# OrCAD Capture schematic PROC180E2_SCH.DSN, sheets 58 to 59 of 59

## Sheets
58 47. CAN_INTERFACE: size C; title: CAN TRANSCEIVER
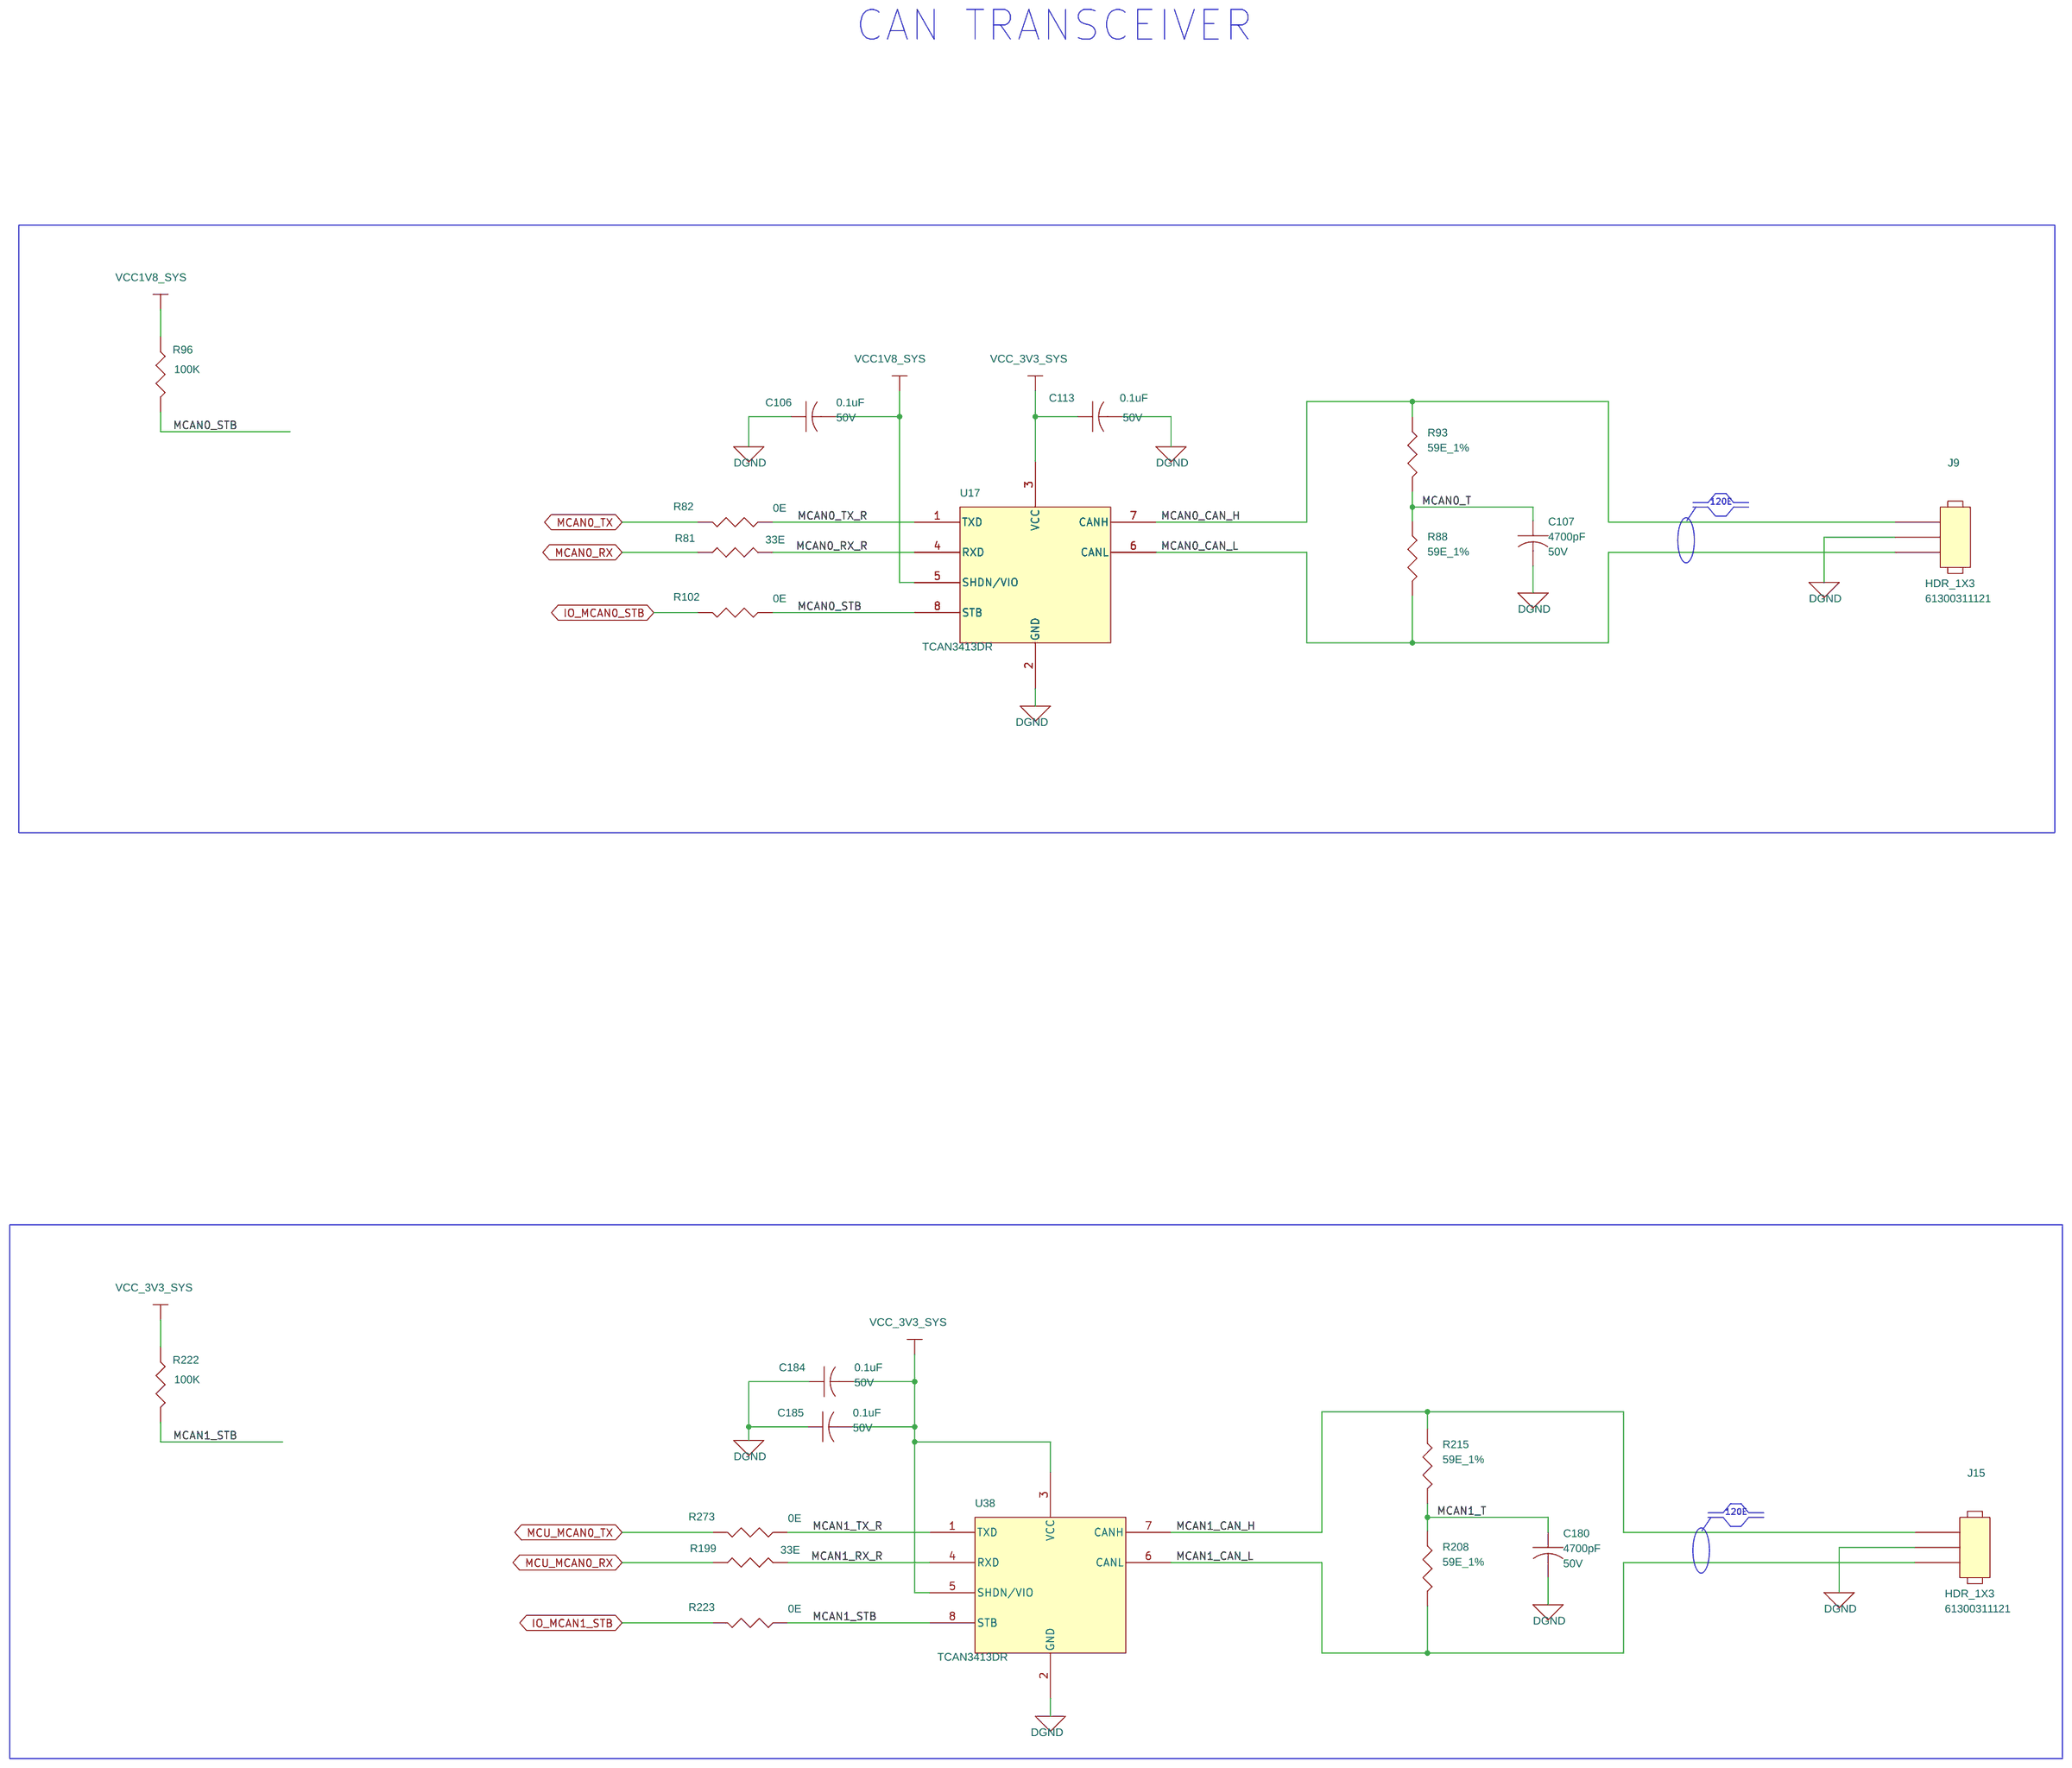
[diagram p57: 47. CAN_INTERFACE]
59 59. MOUNTING HARDWARE: title: MOUNTING HARDWARE
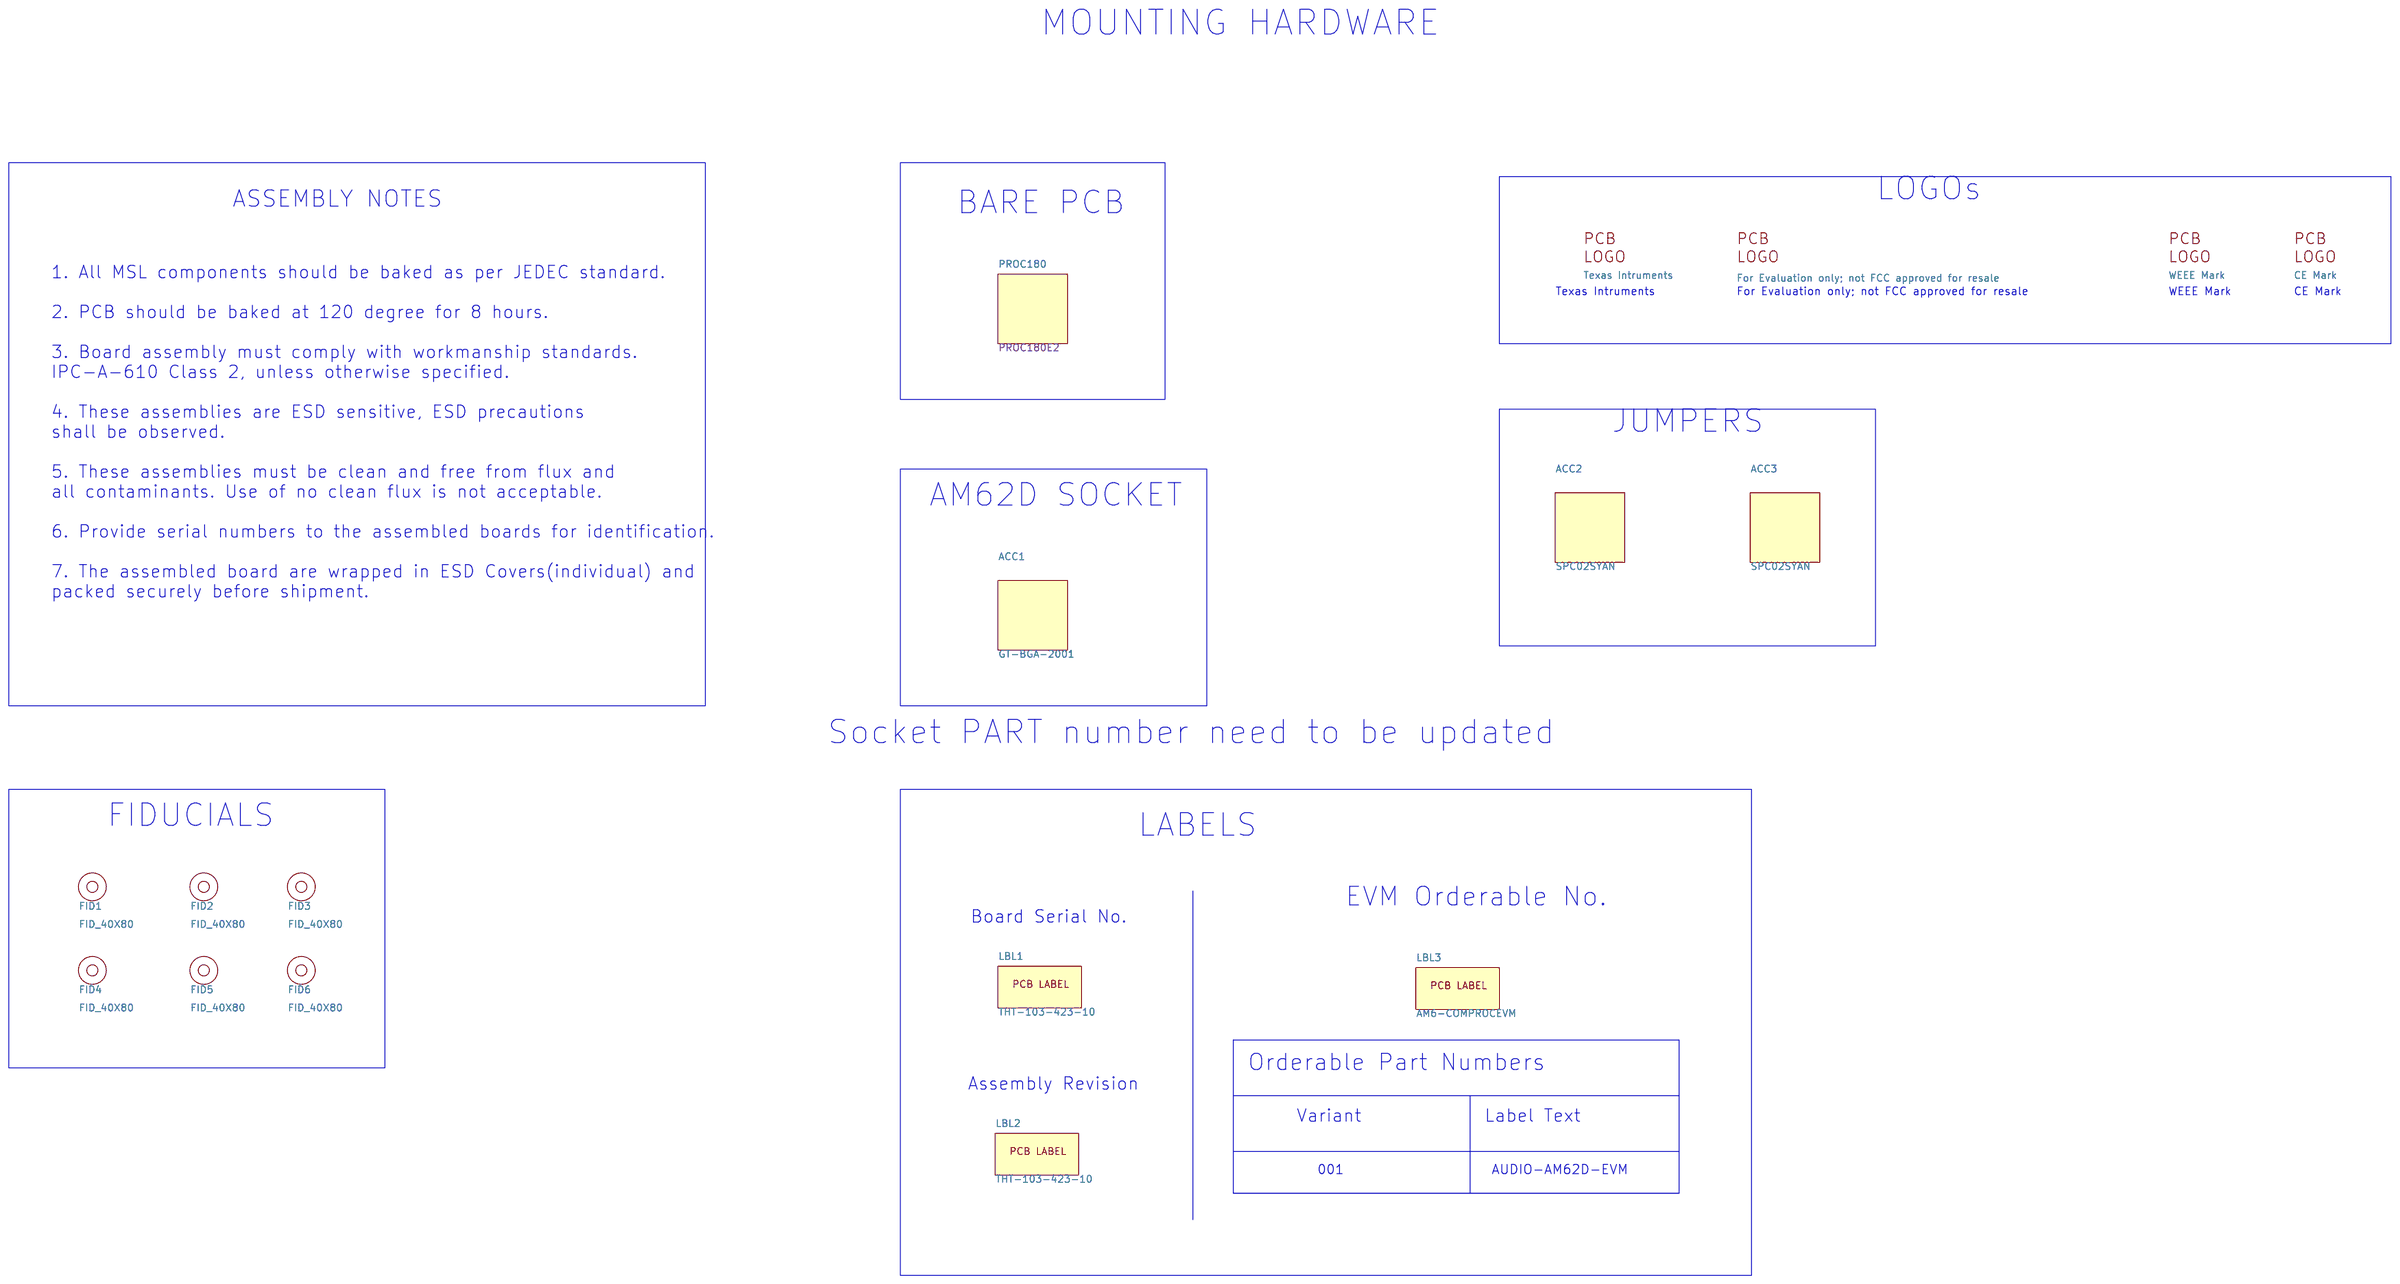
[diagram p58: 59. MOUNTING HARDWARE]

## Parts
sheet 47. CAN_INTERFACE
C106  0.1uF  [CAP0402_0-75]
C107  4700pF  [CAP0402_0-75]
C113  0.1uF  [CAP0402_0-75]
C180  4700pF  [CAP0402_0-75]
C184  0.1uF  [CAP0402_0-75]
C185  0.1uF  [CAP0402_0-75]
J9  HDR_1X3  [HDR_1X3_100_S_T]
J15  HDR_1X3  [HDR_1X3_100_S_T]
R81  33E  [RES0402_0-5]
R82  0E  [RES0402_0-5]
R88  59E_1%  [RES0402_0-5]
R93  59E_1%  [RES0402_0-5]
R96  100K  [RES0201_0-5]
R102  0E  [RES0402_0-5]
R199  33E  [RES0402_0-5]
R208  59E_1%  [RES0402_0-5]
R215  59E_1%  [RES0402_0-5]
R222  100K  [RES0201_0-5]
R223  0E  [RES0402_0-5]
R273  0E  [RES0402_0-5]
U17  TCAN3413DR  [SOIC8_1-8]
U38  TCAN3413DR  [SOIC8_1-8]
sheet 59. MOUNTING HARDWARE
ACC1  GT-BGA-2001  [BGASKT484_GT-BGA-2001_910X910_10-7]
ACC2  SPC02SYAN  [NA]
ACC3  SPC02SYAN  [NA]
FID1  FID_40X80  [FID_40X80]
FID2  FID_40X80  [FID_40X80]
FID3  FID_40X80  [FID_40X80]
FID4  FID_40X80  [FID_40X80]
FID5  FID_40X80  [FID_40X80]
FID6  FID_40X80  [FID_40X80]
LBL1  THT-103-423-10  [NA]
LBL2  THT-103-423-10  [NA]
LBL3  AM6-COMPROCEVM  [NA]
LOGO1  Texas Intruments  [TI_Stacked_Overlay_Small]
LOGO2  For Evaluation only; not FCC approved for resale  [FCC_disclaimer]
LOGO3  WEEE Mark  [TI_Stacked_Overlay_Small]
LOGO4  CE Mark  [TI_Stacked_Overlay_Small]
PCB1  PROC180

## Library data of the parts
C106 C113 C184 C185 = CAP: CAP CERAMIC 0.1uF 50V 10% X7R AUTO 0402; Automotive Alternate_mfr_name: TDK; Automotive Alternate_mfr_part_number: CGA2B1X7R1C104K050BC; Chkd/date: MANIRAJA/250221; Crtd /date: ALVY/240221; Custom_Duty: 15%; Customs_HS_Code: 85322990; Direct Alternate_mfr_name: MURATA; Direct Alternate_mfr_part_number: GCM155R71C104JA55D; Distributor_name: MOUSER; Distributor_part_number: 81-GRT155R71H104KE1D; Footprint Path: Y:\MIS_DATABASE\Library\ALTIUM_TOOL\PCB_FOOTPRINTS\Altium_Footprint_Lib.PcbLib; Height: 0.55MM; Library Path: Y:\MIS_DATABASE\Library\ALTIUM_TOOL\SCHEMATICS_PARTS\MS_DISCRETE_Library.schlib; Mfr_name: MURATA; Mfr_part_number: GRT155R71H104KE01D; Mistral Part No: 120019030005-R; Package: 0402; Part_type: CAPACITORS\CERAMIC; Project: TI_DRA821 SK EVM BRD; RoHS: RoHS; Temperature: -55°C+125°C; Tolerance: 10%; Voltage: 50V; Wattage: NA; Weight: NA; Datasheet: Y:\MIS_DATABASE\DATASHEETS\CAPACITORS\GRT155R71H104KE01.PDF
C107 C180 = CAP: CAP CERAMIC 4700pF 50V 10% X7R 0402; Automotive Alternate_mfr_name: TDK; Automotive Alternate_mfr_part_number: CGA2B2X7R1H472K050BA; Chkd/date: MANIRAJA/040419; Crtd /date: MANIRAJA/040419; Custom_Duty: 15%; Customs_HS_Code: 85322990; Direct Alternate_mfr_name: SAMSUNG; Direct Alternate_mfr_part_number: CL05B472KB5NNNC; Distributor_name: DIGIKEY; Distributor_part_number: 490-1308-1-ND; Footprint Path: Y:\MIS_DATABASE\Library\ALTIUM_TOOL\PCB_FOOTPRINTS\Altium_Footprint_Lib.PcbLib; Height: 0.55MM; Library Path: Y:\MIS_DATABASE\Library\ALTIUM_TOOL\SCHEMATICS_PARTS\MS_DISCRETE_Library.schlib; Mfr_name: MURATA; Mfr_part_number: GRM155R71H472KA01D; Mistral Part No: 120009030440-R; Package: 0402; Part_type: CAPACITORS\CERAMIC; Project: RED EYE; RoHS: RoHS; Temperature: -55°C+125°C; Tolerance: 10%; Voltage: 50V; Wattage: NA; Weight: 0.65mg; Datasheet: Y:\MIS_DATABASE\DATASHEETS\CAPACITORS\GRM155R71H472KA01.PDF
J9 J15 = HEADER_3X1: CON HDR 1X3 2.54MM PITCH ST TH; Chkd/date: VASANTHA/211015; Crtd /date: VASANTHA/211015; Custom_Duty: 24%; Customs_HS_Code: 85369090; Distributor_name: DIGIKEY; Distributor_part_number: 732-5316-ND; Height: 8.54MM; Mfr_name: WURTH ELECTRONICS INC; Mfr_part_number: 61300311121; Mistral Part No: 150015100037-R; Package: THRU-HOLE; Part_type: CONNECTOR\HEADERS; Project: CYPHY_ROADKILL; RoHS: RoHS; Temperature: NA; Tolerance: NA; Voltage: NA; Wattage: NA; Weight: NA; Datasheet: Y:\MIS_DATABASE\DATASHEETS\CONNECTORS\6130XXX.PDF
R81 R199 = RESISTOR: RES 33E 1/10W 5% 0402; Chkd/date: VASANTHA/201216; Crtd /date: GEETHA/190406; Custom_Duty: 15%; Customs_HS_Code: 85332119; Distributor_name: DIGIKEY; Distributor_part_number: P33JCT-ND; Footprint Path: Y:\MIS_DATABASE\Library\ALTIUM_TOOL\PCB_FOOTPRINTS\Altium_Footprint_Lib.PcbLib; Height: 0.40MM; Library Path: Y:\MIS_DATABASE\Library\ALTIUM_TOOL\SCHEMATICS_PARTS\MS_DISCRETE_Library.schlib; Mfr_name: PANASONIC-ECG; Mfr_part_number: ERJ-2GEJ330X; Mistral Part No: 110009030699-R; Package: 0402; Part_type: RESISTORS\FIXED; Project: RED EYE; RoHS: RoHS; Temperature: -55°C+155°C; Tolerance: 5%; Voltage: NA; Wattage: 1/10W; Weight: 0.8mg; Datasheet: Y:\MIS_DATABASE\DATASHEETS\RESISTORS\PAN-ERJSER_NOV17.PDF
R82 R102 R223 R273 = RESISTOR: RES 0E 1/10W JUMPER 0402; Chkd/date: VASANTHA/061216; Crtd /date: NAVEED/201014; Custom_Duty: 15%; Customs_HS_Code: 85332119; Distributor_name: DIGIKEY; Distributor_part_number: P0.0JCT-ND; Footprint Path: Y:\MIS_DATABASE\Library\ALTIUM_TOOL\PCB_FOOTPRINTS\Altium_Footprint_Lib.PcbLib; Height: 0.40MM; IBISSP_MODLES: VALUE REPEATING 2 TIME; Library Path: Y:\MIS_DATABASE\Library\ALTIUM_TOOL\SCHEMATICS_PARTS\MS_DISCRETE_Library.schlib; Mfr_name: PANASONIC-ECG; Mfr_part_number: ERJ-2GE0R00X; Mistral Part No: 110018030052-R; Package: 0402; Part_type: RESISTORS\FIXED; Project: AEGIS POM; RoHS: RoHS; Temperature: -55°C+155°C; Tolerance: NA; Voltage: NA; Wattage: 1/10W; Weight: 0.8mg; Datasheet: Y:\MIS_DATABASE\DATASHEETS\RESISTORS\PAN-ERJSER_NOV17.PDF
R88 R93 R208 R215 = RESISTOR: RES 59E 1/10W 1% 0402; Chkd/date: MAZHAR/151208; Crtd /date: USMAN/031208; Custom_Duty: 15%; Customs_HS_Code: 85332119; Distributor_name: DIGIKEY; Distributor_part_number: P59.0LCT-ND; Footprint Path: Y:\MIS_DATABASE\Library\ALTIUM_TOOL\PCB_FOOTPRINTS\Altium_Footprint_Lib.PcbLib; Height: 0.40MM; Library Path: Y:\MIS_DATABASE\Library\ALTIUM_TOOL\SCHEMATICS_PARTS\MS_DISCRETE_Library.schlib; Mfr_name: PANASONIC-ECG; Mfr_part_number: ERJ-2RKF59R0X; Mistral Part No: 110009031010-R; Package: 0402; Part_type: RESISTORS\FIXED; Project: KHAN_HSST; RoHS: RoHS; Temperature: -55°C+155°C; Tolerance: 1%; Voltage: NA; Wattage: 1/10W; Weight: 0.8mg; Datasheet: Y:\MIS_DATABASE\DATASHEETS\RESISTORS\PAN-ERJSER_NOV17.PDF
R96 R222 = RESISTOR: RES 100K 1/20W 5% 0201; Chkd/date: MANIRAJA/050517; Crtd /date: MANIRAJA/050517; Custom_Duty: 15%; Customs_HS_Code: 85332119; Distributor_name: DIGIKEY; Distributor_part_number: 311-100KNCT-ND; Footprint Path: Y:\MIS_DATABASE\Library\ALTIUM_TOOL\PCB_FOOTPRINTS\Altium_Footprint_Lib.PcbLib; Height: 0.26MM; Library Path: Y:\MIS_DATABASE\Library\ALTIUM_TOOL\SCHEMATICS_PARTS\MS_DISCRETE_Library.schlib; Mfr_name: YAGEO AMERICA; Mfr_part_number: RC0201JR-07100KL; Mistral Part No: 110009030176-R; Package: 0201; Part_type: RESISTORS\FIXED; Project: GOLDEN-I LITE; RoHS: RoHS; Temperature: -55°C+125°C; Tolerance: 5%; Voltage: NA; Wattage: 1/20W; Weight: 0.17mg; Datasheet: Y:\MIS_DATABASE\DATASHEETS\RESISTORS\RCXXXXL-SER_MAR18.PDF
U17 U38 = TCAN3413DR_SOIC8: IC 3.3V CAN FD TRANSCEIVERS WITH STANDBY MODE AND +/-58V BUS STANDOFF SOIC8; Crtd /date: TAMILARASU/221223; Custom_Duty: 15%; Customs_HS_Code: 85423100; Distributor_name: NA; Distributor_part_number: NA; Footprint Path: Y:\MIS_DATABASE\Library\ALTIUM_TOOL\PCB_FOOTPRINTS\Altium_Footprint_Lib.PcbLib; Height: 1.80MM; Library Path: Y:\MIS_DATABASE\Library\ALTIUM_TOOL\SCHEMATICS_PARTS\MS_TELECOM_Library.schlib; Mfr_name: TEXAS INSTRUMENTS; Mistral Part No: 140123120005-R; Package: SOIC8; Part_type: ICS\TELECOM\TRANSCEIVER; Project: AM62D-EVM; RoHS: RoHS; Temperature: -40°C+125°C; Tolerance: NA; Voltage: NA; Wattage: NA; Weight: NA; Datasheet: Y:\MIS_DATABASE\DATASHEETS\ICS\TELECOM\TCAN3413.PDF
ACC1 = ACCESSORY: ACCESSORIE BGA SOCKET AM62A SVB SoC MICROPROCESSOR FCBGA484; Chkd/date: ALVY/180422; Crtd /date: ALVY/180422; Custom_Duty: NA; Customs_HS_Code: NA; Distributor_name: NA; Distributor_part_number: NA; Footprint Path: NA; Height: 10.69MM; Library Path: NA; Mfr_name: IRONWOOD ELECTRONICS; Mistral Part No: 160022040013; Package: FCBGA484; Part_type: ACCESSORIES; Project: TI_AM62A_SVB_BRD; RoHS: NA; Temperature: NA; Tolerance: NA; Voltage: NA; Wattage: NA; Weight: NA; Datasheet: Y:\MIS_DATABASE\DATASHEETS\MISC\ACCESSORIES\GT-BGA-2001.PDF
ACC2 ACC3 = ACCESSORY: ACCESSORIE JUMPER SHORTING GOLD FLASH; Chkd/date: SUHAS\211010; Crtd /date: USMAN/301208; Distributor_name: DIGIKEY; Distributor_part_number: S9001-ND; Footprint Path: Y:\MIS_DATABASE\Library\ALTIUM_TOOL\PCB_FOOTPRINTS\Altium_Footprint_Lib.PcbLib; Library Path: Y:\MIS_DATABASE\Library\ALTIUM_TOOL\SCHEMATICS_PARTS\MS_MECHANICAL_Library.schlib; Mfr_name: SULLINS CONNECTOR; Mistral Part No: 160009030153-R; Part_type: ACCESSORIES; Project: SMART VIEW_NVR; RoHS: RoHS; Temperature: -55°C+105°C; Datasheet: Y:\MIS_DATABASE\DATASHEETS\MISC\MODULES\SPC02SYAN.PDF
FID1-FID6 = Fiducial
LBL1 LBL2 = ACCESSORY_THT-3-423-10: ACCESSORIE 1 WORKHORSE POLYSTER LABLE 0.25" X 1"; Chkd/date: MANIRAJA/270218; Crtd /date: ALVY/260218; Footprint Path: Y:\MIS_DATABASE\Library\ALTIUM_TOOL\PCB_FOOTPRINTS\Altium_Footprint_Lib.PcbLib; Library Path: Y:\MIS_DATABASE\Library\ALTIUM_TOOL\SCHEMATICS_PARTS\MS_MECHANICAL_Library.schlib; Mfr_name: BRADY; Mistral Part No: 160018020185; Part_type: ACCESSORIES; Project: TI_MAXIE_CPB
LBL3 = ACCESSORY_THT-3-423-10: ACCESSORIE 1 WORKHORSE POLYSTER LABLE 0.25" X 1"; Chkd/date: MANIRAJA/270218; Crtd /date: ALVY/260218; Footprint Path: Y:\MIS_DATABASE\Library\ALTIUM_TOOL\PCB_FOOTPRINTS\Altium_Footprint_Lib.PcbLib; Library Path: Y:\MIS_DATABASE\Library\ALTIUM_TOOL\SCHEMATICS_PARTS\MS_MECHANICAL_Library.schlib; Mfr_name: BRADY; Mfr_part_number: THT-103-423-10; Mistral Part No: 160018020185; Part_type: ACCESSORIES; Project: TI_MAXIE_CPB
LOGO1 LOGO3 LOGO4 = TI_Logo
LOGO2 = FCC_disclaimer
PCB1 = PCB_0: AM62D EVM; Mfr_part_number: PROC180E2; Mistral Part No: FY22-23/00176000401

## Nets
DGND: C106.1 C107.2 C113.2 C180.2 C184.1 C185.1 J9.2 J15.2 U17.2(GND) U38.2(GND) ; also on sheet 1 2 3 4 5 6 7 8 9 10 12 13 14 16 17 18 19 20 21 22 31 32 33 34 35 36 37 38 39 40 41 42 43 44 45 46 47 48 49 50 51 52 53 54 55 56 57
VCC1V8_SYS: C106.2 R96.1 U17.5(SHDN/VIO) ; also on sheet 1 2 4 6 7 10 20 21 22 33 37 38 39 42 43 49 50 52 53 54 55 56 57
VCC_3V3_SYS: C113.1 C184.2 C185.2 R222.1 U17.3(VCC) U38.3(VCC) U38.5(SHDN/VIO) ; also on sheet 1 2 3 6 10 14 17 18 19 20 22 31 33 37 38 40 41 42 45 46 48 49 50 51 52 53 54 55 56 57
IO_MCAN0_STB: R102.2 ; also on sheet 55
IO_MCAN1_STB: R223.2 ; also on sheet 55
MCAN0_CAN_H: J9.1 R93.1 U17.7(CANH)
MCAN0_CAN_L: J9.3 R88.2 U17.6(CANL)
MCAN0_RX: R81.1 ; also on sheet 7
MCAN0_RX_R: R81.2 U17.4(RXD)
MCAN0_STB: R96.2 R102.1 U17.8(STB)
MCAN0_T: C107.1 R88.1 R93.2
MCAN0_TX: R82.2 ; also on sheet 7
MCAN0_TX_R: R82.1 U17.1(TXD)
MCAN1_CAN_H: J15.1 R215.1 U38.7(CANH)
MCAN1_CAN_L: J15.3 R208.2 U38.6(CANL)
MCAN1_RX_R: R199.2 U38.4(RXD)
MCAN1_STB: R222.2 R223.1 U38.8(STB)
MCAN1_T: C180.1 R208.1 R215.2
MCAN1_TX_R: R273.1 U38.1(TXD)
MCU_MCAN0_RX: R199.1 ; also on sheet 48
MCU_MCAN0_TX: R273.2 ; also on sheet 48

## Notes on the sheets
sheet 58
- CAN TRANSCEIVER
- 120E
- 120E
sheet 59
- MOUNTING HARDWARE
- LOGOs
- ASSEMBLY NOTES
- BARE PCB
- 1. All MSL components should be baked as per JEDEC standard.
  2. PCB should be baked at 120 degree for 8 hours.
  3. Board assembly must comply with workmanship standards.
  IPC-A-610 Class 2, unless otherwise specified.
  4. These assemblies are ESD sensitive, ESD precautions
  shall be observed.
  5. These assemblies must be clean and free from flux and
  all contaminants. Use of no clean flux is not acceptable.
  6. Provide serial numbers to the assembled boards for identification.
  7. The assembled board are wrapped in ESD Covers(individual) and
  packed securely before shipment.
- Texas Intruments
- For Evaluation only; not FCC approved for resale
- WEEE Mark
- CE Mark
- JUMPERS
- AM62D SOCKET
- Socket PART number need to be updated
- FIDUCIALS
- LABELS
- EVM Orderable No.
- Board Serial No.
- Orderable Part Numbers
- Assembly Revision
- Variant
- Label Text
- 001
- AUDIO-AM62D-EVM
